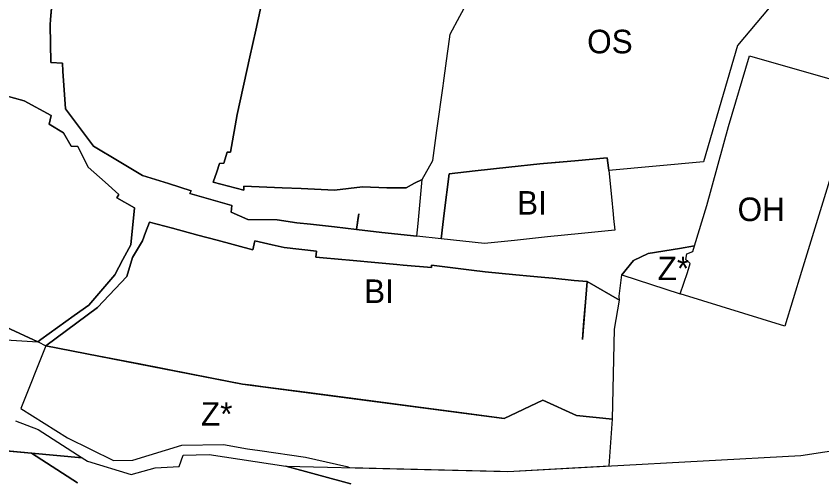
# Model space of a CAD drawing. Extents: x -521621 to -516769, y -1190068 to -1185078.
# Drawn here: x -518947.5 to -518605.8, y -1187581.5 to -1187385.7 of the extents above; entities that cross this region are included whole.
import ezdxf

# ---------------------------------------------------------------- set-up
doc = ezdxf.new("R2010")
doc.units = 0
for name, color, linetype in [('bydleni_s', 7, 'Continuous'), ('s_zelen_s', 7, 'Continuous'), ('v_infrastr_n', 7, 'Continuous'), ('v_infrastr_s', 7, 'Continuous')]:
    doc.layers.add(name, color=color, linetype=linetype)

msp = doc.modelspace()

# ---------------------------------------------------------------- linework, layer by layer
at = {"layer": 'bydleni_s'}
for p, q in [((-518932.05, -1187377.16), (-518932.92, -1187387.05)), ((-518927.67, -1187409), (-518926.64, -1187424.96)), ((-518944.16, -1187421.61), (-518959.17, -1187417.44)), ((-518926.64, -1187424.96), (-518914.68, -1187440.86)), ((-518903.8, -1187447.35), (-518894, -1187453.2)), ((-518894, -1187453.2), (-518882.9, -1187456.67)), ((-518836.82, -1187472.11), (-518828.49, -1187473.27)), ((-518803.14, -1187476.15), (-518792.4, -1187477.37))]:
    msp.add_line(p, q, dxfattribs=at)
for points in [[(-518845.88, -1187391.58), (-518843.58, -1187381.09)], [(-518932.92, -1187387.05), (-518933.12, -1187389.31), (-518932.89, -1187405.29), (-518927.88, -1187405.67), (-518927.67, -1187409)], [(-518848.39, -1187402.98), (-518845.88, -1187391.58)], [(-518853.76, -1187427.43), (-518848.39, -1187402.98)], [(-518927.49, -1187435.19), (-518933.51, -1187431.48), (-518932.74, -1187427.78), (-518944.16, -1187421.61)], [(-518856.62, -1187443.41), (-518853.76, -1187427.43)], [(-518917, -1187449.69), (-518921.32, -1187440.9), (-518924.25, -1187440.74), (-518927.49, -1187435.19)], [(-518914.68, -1187440.86), (-518903.8, -1187447.35)], [(-518812.48, -1187459.46), (-518826.72, -1187458.83), (-518834.66, -1187458.48), (-518850.91, -1187457.76), (-518851.02, -1187459.49), (-518864.02, -1187456.14), (-518862.48, -1187451.72), (-518861.25, -1187448.19), (-518859.39, -1187448.04), (-518858.04, -1187443.34), (-518856.62, -1187443.41)], [(-518718.72, -1187447.75), (-518710.58, -1187447.02), (-518696.85, -1187445.8), (-518696.32, -1187449.96)], [(-518904.8, -1187462.66), (-518904.03, -1187461.27), (-518909.81, -1187456.11), (-518917, -1187449.69)], [(-518752.85, -1187451.31), (-518738.51, -1187449.76)], [(-518738.51, -1187449.76), (-518725.4, -1187448.34), (-518723.93, -1187448.21)], [(-518723.93, -1187448.21), (-518718.72, -1187447.75)], [(-518696.32, -1187449.96), (-518696.16, -1187451.2)], [(-518748.94, -1187482.06), (-518767.34, -1187480.12), (-518766.59, -1187474.06), (-518765.99, -1187469.27), (-518763.91, -1187452.51), (-518752.85, -1187451.31)], [(-518696.16, -1187451.2), (-518695.08, -1187462.26)], [(-518882.9, -1187456.67), (-518873.24, -1187459.69), (-518873.86, -1187460.84), (-518870.83, -1187461.72)], [(-518775.29, -1187454.94), (-518778.61, -1187456.52), (-518782.15, -1187458.45), (-518790.26, -1187458.53), (-518800.67, -1187457.99)], [(-518792.4, -1187477.37), (-518777.56, -1187479.05), (-518777.05, -1187473.63), (-518775.29, -1187454.94)], [(-518800.67, -1187457.99), (-518812.48, -1187459.46)], [(-518902.24, -1187488.89), (-518898.94, -1187482.6), (-518897.32, -1187467.02), (-518904.8, -1187462.66)], [(-518870.83, -1187461.72), (-518856.04, -1187466.01)], [(-518695.08, -1187462.26), (-518694.35, -1187469.7), (-518694.17, -1187471.56), (-518693.69, -1187476.43), (-518707.69, -1187477.86)], [(-518856.04, -1187466.01), (-518856.27, -1187468.87), (-518849.32, -1187471.96)], [(-518802.23, -1187469.46), (-518803.14, -1187476.15)], [(-518802.45, -1187471.05), (-518802.23, -1187469.46)], [(-518881.22, -1187475.65), (-518890.99, -1187473.04), (-518892.64, -1187477.49), (-518893.92, -1187480.91), (-518898.25, -1187488.08), (-518900.64, -1187496.03)], [(-518849.32, -1187471.96), (-518836.82, -1187472.11)], [(-518828.49, -1187473.27), (-518822.76, -1187473.92), (-518812.55, -1187475.08)], [(-518803.14, -1187476.15), (-518802.45, -1187471.05)], [(-518862.27, -1187480.71), (-518870.45, -1187478.53), (-518881.22, -1187475.65)], [(-518812.55, -1187475.08), (-518803.14, -1187476.15)], [(-518707.69, -1187477.86), (-518722.16, -1187479.33)], [(-518847.19, -1187484.8), (-518862.27, -1187480.71)], [(-518838.92, -1187482.67), (-518846.32, -1187480.98), (-518847.19, -1187484.8)], [(-518736.2, -1187480.76), (-518748.94, -1187482.06)], [(-518722.16, -1187479.33), (-518736.2, -1187480.76)], [(-518820.39, -1187487.85), (-518820.2, -1187485.37), (-518833.81, -1187483.84), (-518838.92, -1187482.67)], [(-518804.62, -1187489.3), (-518817.26, -1187488.14), (-518820.39, -1187487.85)], [(-518922.88, -1187512.61), (-518916.76, -1187508.22), (-518905.65, -1187495.41), (-518902.24, -1187488.89)], [(-518795.44, -1187490.15), (-518804.62, -1187489.3)], [(-518786.13, -1187491.01), (-518795.44, -1187490.15)], [(-518771.39, -1187492.27), (-518783.43, -1187491.24), (-518786.13, -1187491.01)], [(-518754.36, -1187493.38), (-518771.31, -1187491.25), (-518771.39, -1187492.27)], [(-518735.57, -1187495.33), (-518748.63, -1187494.1), (-518754.36, -1187493.38)], [(-518900.64, -1187496.03), (-518912.98, -1187509.3), (-518934.9, -1187525.51), (-518912.46, -1187529.87)], [(-518719.88, -1187496.83), (-518723.32, -1187496.49), (-518729.53, -1187495.9), (-518735.57, -1187495.33)], [(-518705.42, -1187498.27), (-518710.81, -1187497.73), (-518719.88, -1187496.83)], [(-518709.93, -1187555.02), (-518694.65, -1187556.56), (-518693.77, -1187518.41), (-518691.62, -1187506.18), (-518705.42, -1187498.27)], [(-518705.42, -1187498.27), (-518707.36, -1187522.74)], [(-518707.36, -1187522.74), (-518706.74, -1187514.82), (-518706.62, -1187513.35), (-518705.98, -1187505.29), (-518705.42, -1187498.27)], [(-518937.12, -1187522.83), (-518922.88, -1187512.61)], [(-518951.77, -1187517.59), (-518938.37, -1187523.73), (-518937.12, -1187522.83)], [(-518912.46, -1187529.87), (-518851.56, -1187541.72), (-518740.6, -1187556.29)], [(-518740.6, -1187556.29), (-518724.13, -1187548.54)], [(-518724.13, -1187548.54), (-518709.93, -1187555.02)]]:
    msp.add_lwpolyline(points, dxfattribs=at)
at = {"layer": 's_zelen_s'}
for points in [[(-518843.58, -1187381.09), (-518845.88, -1187391.58), (-518848.39, -1187402.98), (-518853.76, -1187427.43), (-518856.62, -1187443.41), (-518858.04, -1187443.34), (-518859.39, -1187448.04), (-518861.25, -1187448.19), (-518862.48, -1187451.72), (-518864.02, -1187456.14), (-518851.02, -1187459.49), (-518850.91, -1187457.76), (-518834.66, -1187458.48), (-518826.72, -1187458.83), (-518812.48, -1187459.46), (-518800.67, -1187457.99), (-518790.26, -1187458.53), (-518782.15, -1187458.45), (-518778.61, -1187456.52), (-518775.29, -1187454.94), (-518770.81, -1187446.92), (-518769.08, -1187434.18), (-518766.49, -1187415.2), (-518766.33, -1187414.02), (-518765.03, -1187404.58), (-518763.78, -1187395.47), (-518763.48, -1187393.29), (-518759.4, -1187385.65), (-518755.32, -1187377.99)], [(-518690.72, -1187495.41), (-518665.87, -1187503.51), (-518662.85, -1187494.33), (-518661.63, -1187490.63), (-518663.48, -1187488.85), (-518663.09, -1187486.46), (-518660.55, -1187485.54), (-518659.8, -1187483.07), (-518666.18, -1187484.15), (-518679.53, -1187486.38), (-518685.7, -1187489.32), (-518690.72, -1187495.41)], [(-518938.37, -1187523.73), (-518951.77, -1187517.59)], [(-518951.91, -1187522.96), (-518945.14, -1187523.34), (-518938.37, -1187523.73)], [(-518912.46, -1187529.87), (-518934.9, -1187525.51), (-518945.55, -1187552.05)], [(-518895.41, -1187533.19), (-518912.46, -1187529.87)], [(-518873.16, -1187537.52), (-518895.41, -1187533.19)], [(-518847.74, -1187542.22), (-518851.56, -1187541.72), (-518873.16, -1187537.52)], [(-518842.76, -1187542.87), (-518847.74, -1187542.22)], [(-518824.03, -1187545.33), (-518842.76, -1187542.87)], [(-518806.78, -1187547.6), (-518824.03, -1187545.33)], [(-518791.71, -1187549.58), (-518806.78, -1187547.6)], [(-518775.72, -1187551.68), (-518791.71, -1187549.58)], [(-518724.13, -1187548.54), (-518740.6, -1187556.29)], [(-518709.93, -1187555.02), (-518724.13, -1187548.54)], [(-518945.55, -1187552.05), (-518925.72, -1187564.47)], [(-518758.46, -1187553.94), (-518775.72, -1187551.68)], [(-518740.6, -1187556.29), (-518758.46, -1187553.94)], [(-518696.09, -1187576.42), (-518694.65, -1187556.56), (-518709.93, -1187555.02)], [(-518925.72, -1187564.47), (-518906.27, -1187574.2)], [(-518906.27, -1187574.2), (-518898.01, -1187573.96), (-518877.26, -1187567.56)], [(-518877.26, -1187567.56), (-518859.55, -1187567.37), (-518849.36, -1187569.22)], [(-518849.36, -1187569.22), (-518844.12, -1187569.84)], [(-518844.12, -1187569.84), (-518824.83, -1187572.77)], [(-518824.83, -1187572.77), (-518807.23, -1187576.63)], [(-518807.23, -1187576.63), (-518806.16, -1187577.16), (-518794.79, -1187577.43)], [(-518711.57, -1187577.26), (-518696.09, -1187576.42)], [(-518794.79, -1187577.43), (-518777.29, -1187577.85)], [(-518777.29, -1187577.85), (-518760.12, -1187578.26)], [(-518760.12, -1187578.26), (-518742.31, -1187578.69)], [(-518742.31, -1187578.69), (-518739.02, -1187578.77), (-518726.53, -1187578.08)], [(-518726.53, -1187578.08), (-518711.57, -1187577.26)]]:
    msp.add_lwpolyline(points, dxfattribs=at)
at = {"layer": 'v_infrastr_n'}
for points in [[(-519790.94, -1187475.66), (-519421.47, -1187513.5), (-519006.29, -1187565.08), (-518941.03, -1187571.03), (-518921.54, -1187583.59)], [(-518805.65, -1187584), (-518833.12, -1187576.51), (-518739.02, -1187578.77), (-518614.79, -1187571.96), (-518434.34, -1187544.46), (-518423, -1187557.03), (-518404.48, -1187539.91), (-518376.14, -1187535.59), (-518368.47, -1187534.43), (-518367.87, -1187534.73), (-518356.76, -1187550.62), (-518347.04, -1187562.81), (-518336.39, -1187572.85), (-518325.58, -1187582.72)], [(-518947.74, -1187557.27), (-518938.14, -1187561), (-518919.53, -1187572.99), (-518941.03, -1187571.03), (-518953.05, -1187569.94)], [(-518921.54, -1187583.59), (-518941.03, -1187571.03), (-518919.53, -1187572.99), (-518917.3, -1187574.43), (-518898.71, -1187580.06), (-518888.6, -1187577.2), (-518878.41, -1187576.74), (-518876.64, -1187571.88), (-518865.68, -1187571.57), (-518833.12, -1187576.51), (-518805.65, -1187584)]]:
    msp.add_lwpolyline(points, dxfattribs=at)
at = {"layer": 'v_infrastr_s'}
for points in [[(-518721.82, -1187297.37), (-518708.66, -1187307.06), (-518653.95, -1187333.99), (-518634.2, -1187343.35), (-518644.03, -1187377.98), (-518628.1, -1187382.14), (-518641.6, -1187398.11), (-518647.62, -1187418.94), (-518656.03, -1187447.42), (-518696.16, -1187451.2), (-518696.32, -1187449.96), (-518696.85, -1187445.8), (-518710.58, -1187447.02)], [(-518926.64, -1187424.96), (-518927.67, -1187409), (-518927.88, -1187405.67), (-518932.89, -1187405.29), (-518933.12, -1187389.31), (-518932.92, -1187387.05), (-518932.05, -1187377.16), (-518931.18, -1187367.13), (-518930.11, -1187354.98), (-518929.8, -1187351.43), (-518928.76, -1187343.71), (-518927.56, -1187334.8), (-518926.51, -1187326.98), (-518925.33, -1187318.25), (-518924.97, -1187315.06)], [(-518597.94, -1187360.53), (-518605.81, -1187356.8), (-518628.1, -1187382.14), (-518641.6, -1187398.11), (-518647.62, -1187418.94), (-518656.03, -1187447.42)], [(-519110.5, -1187377.14), (-519099.69, -1187378.8), (-519089.19, -1187380.42), (-519082.28, -1187381.48), (-519071.47, -1187384.11), (-519052.05, -1187390.16), (-519037.91, -1187394.56), (-519023.63, -1187399.01), (-519017.05, -1187401.06), (-519008.05, -1187403.86), (-518994.45, -1187407.64), (-518982.16, -1187411.05), (-518970.39, -1187414.32), (-518959.17, -1187417.44), (-518944.16, -1187421.61), (-518932.74, -1187427.78)], [(-518763.48, -1187393.29), (-518759.4, -1187385.65)], [(-518765.03, -1187404.58), (-518763.78, -1187395.47)], [(-518763.78, -1187395.47), (-518763.48, -1187393.29)], [(-518659.8, -1187483.07), (-518654.57, -1187465.94), (-518645.46, -1187432.53), (-518636.51, -1187402.51), (-518590.56, -1187415.7), (-518603.76, -1187459.07), (-518614.48, -1187493.95), (-518621.5, -1187517.1), (-518665.87, -1187503.51), (-518662.85, -1187494.33)], [(-518654.57, -1187465.94), (-518645.46, -1187432.53), (-518636.51, -1187402.51)], [(-518636.51, -1187402.51), (-518590.56, -1187415.7)], [(-518766.33, -1187414.02), (-518765.03, -1187404.58)], [(-518763.91, -1187452.51), (-518765.99, -1187469.27), (-518766.59, -1187474.06), (-518767.34, -1187480.12), (-518777.56, -1187479.05), (-518777.05, -1187473.63), (-518775.29, -1187454.94), (-518770.81, -1187446.92), (-518769.08, -1187434.18), (-518766.49, -1187415.2), (-518766.33, -1187414.02)], [(-518894, -1187453.2), (-518903.8, -1187447.35), (-518914.68, -1187440.86), (-518926.64, -1187424.96)], [(-518932.74, -1187427.78), (-518933.51, -1187431.48), (-518927.49, -1187435.19), (-518924.25, -1187440.74), (-518921.32, -1187440.9), (-518917, -1187449.69), (-518909.81, -1187456.11), (-518904.03, -1187461.27), (-518904.8, -1187462.66), (-518897.32, -1187467.02)], [(-518710.58, -1187447.02), (-518723.93, -1187448.21)], [(-518723.93, -1187448.21), (-518725.4, -1187448.34), (-518738.51, -1187449.76), (-518752.85, -1187451.31), (-518763.91, -1187452.51)], [(-518656.03, -1187447.42), (-518696.16, -1187451.2), (-518695.08, -1187462.26), (-518694.35, -1187469.7)], [(-518693.69, -1187476.43), (-518707.69, -1187477.86), (-518722.16, -1187479.33), (-518736.2, -1187480.76), (-518748.94, -1187482.06), (-518767.34, -1187480.12), (-518777.56, -1187479.05), (-518792.4, -1187477.37), (-518803.14, -1187476.15), (-518812.55, -1187475.08), (-518822.76, -1187473.92), (-518828.49, -1187473.27), (-518836.82, -1187472.11), (-518849.32, -1187471.96), (-518856.27, -1187468.87), (-518856.04, -1187466.01), (-518870.83, -1187461.72), (-518873.86, -1187460.84), (-518873.24, -1187459.69), (-518882.9, -1187456.67), (-518894, -1187453.2)], [(-518897.32, -1187467.02), (-518898.94, -1187482.6), (-518902.24, -1187488.89), (-518905.65, -1187495.41)], [(-518690.72, -1187495.41), (-518685.7, -1187489.32), (-518679.53, -1187486.38), (-518666.18, -1187484.15), (-518659.8, -1187483.07), (-518654.57, -1187465.94)], [(-518694.35, -1187469.7), (-518694.17, -1187471.56), (-518693.69, -1187476.43)], [(-518893.92, -1187480.91), (-518892.64, -1187477.49), (-518890.99, -1187473.04), (-518881.22, -1187475.65), (-518870.45, -1187478.53), (-518862.27, -1187480.71)], [(-518900.64, -1187496.03), (-518898.25, -1187488.08), (-518893.92, -1187480.91)], [(-518862.27, -1187480.71), (-518847.19, -1187484.8), (-518846.32, -1187480.98)], [(-518846.32, -1187480.98), (-518838.92, -1187482.67), (-518833.81, -1187483.84), (-518820.2, -1187485.37)], [(-518662.85, -1187494.33), (-518661.63, -1187490.63), (-518663.48, -1187488.85), (-518663.09, -1187486.46), (-518660.55, -1187485.54), (-518659.8, -1187483.07)], [(-518820.2, -1187485.37), (-518820.39, -1187487.85), (-518817.26, -1187488.14), (-518804.62, -1187489.3), (-518795.44, -1187490.15), (-518786.13, -1187491.01), (-518783.43, -1187491.24), (-518771.39, -1187492.27), (-518771.31, -1187491.25)], [(-518771.31, -1187491.25), (-518754.36, -1187493.38), (-518748.63, -1187494.1), (-518735.57, -1187495.33), (-518729.53, -1187495.9), (-518723.32, -1187496.49), (-518719.88, -1187496.83), (-518710.81, -1187497.73), (-518705.42, -1187498.27), (-518691.62, -1187506.18)], [(-518905.65, -1187495.41), (-518916.76, -1187508.22), (-518922.88, -1187512.61), (-518937.12, -1187522.83), (-518938.37, -1187523.73)], [(-518934.9, -1187525.51), (-518912.98, -1187509.3), (-518900.64, -1187496.03)], [(-518691.72, -1187504.38), (-518690.72, -1187495.41)], [(-518691.62, -1187506.18), (-518691.72, -1187504.38)], [(-518938.37, -1187523.73), (-518938.16, -1187523.84)], [(-518938.16, -1187523.84), (-518934.9, -1187525.51)]]:
    msp.add_lwpolyline(points, dxfattribs=at)

# ---------------------------------------------------------------- texts
at = {"layer": 'bydleni_s'}
for p in [(-518735.1, -1187469.85), (-518799.96, -1187507.34)]:
    msp.add_text('BI', height=10, dxfattribs=at).set_placement(p)
at = {"layer": 's_zelen_s'}
for p in [(-518675.47, -1187497.64), (-518869.17, -1187559.39)]:
    msp.add_text('Z*', height=10, dxfattribs=at).set_placement(p)
at = {"layer": 'v_infrastr_s'}
for s, p in [('OS', (-518705.37, -1187401.44)), ('OH', (-518641.57, -1187472.59))]:
    msp.add_text(s, height=10, dxfattribs=at).set_placement(p)

doc.saveas('drawing.dxf')
